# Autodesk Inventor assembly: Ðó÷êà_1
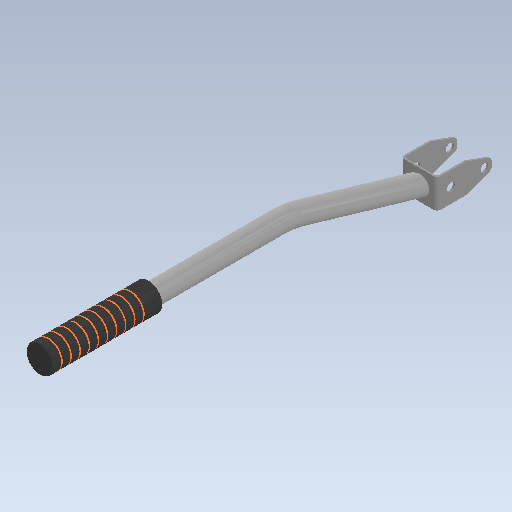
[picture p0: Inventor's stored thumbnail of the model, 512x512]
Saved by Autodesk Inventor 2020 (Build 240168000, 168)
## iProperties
Created: 1900-01
Part Number: Ðó÷êà_1
Document SubType Name: Assembly
Designer: bruno
Author: bruno
Revision Number: ANYUNSPECIFIED
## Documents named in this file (4)
- C:\Users\bruno\Documents\1-Cours-2022-23\1SI\2. Cinématique\Hoverboard\Inventor-Hoverboard\Ðó÷êà_1.iam
- C:\Users\bruno\Documents\1-Cours-2022-23\1SI\2. Cinématique\Hoverboard\Inventor-Hoverboard\Òðóáà ðó÷êè_1.ipt
- C:\Users\bruno\Documents\1-Cours-2022-23\1SI\2. Cinématique\Hoverboard\Inventor-Hoverboard\Âèëêà ðó÷êè_1.ipt
- C:\Users\bruno\Documents\1-Cours-2022-23\1SI\2. Cinématique\Hoverboard\Inventor-Hoverboard\HANDLE GRIP_1.ipt
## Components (3 placed, 3 different names)
1. 34
2. 35
3. 36
